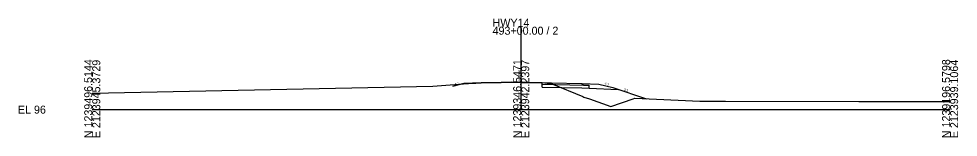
# Model space of a CAD drawing. Extents: x -26 to 303, y -10 to 11521.
# Drawn here: x -25.7 to 302.8, y 4490.3 to 4531.9 of the extents above; entities that cross this region are included whole.
import ezdxf

# ---------------------------------------------------------------- set-up
doc = ezdxf.new("R2010")
doc.units = 0
for name, color, linetype in [('XS_CELL', 7, 'Continuous'), ('XS_P_FINISHED_GRADE', 7, 'Continuous'), ('XS_P_SUBGRADE_GRANULAR', 7, 'Continuous'), ('XS_P_SUBGRADE_LEVELING', 7, 'Continuous'), ('XS_P_SUBGRADE_PAVEMENT', 7, 'Continuous'), ('XS_P_TX_FS_BS', 7, 'Continuous'), ('XS_X_GROUND', 7, 'Continuous'), ('XS_X_GROUND_TX', 7, 'Continuous')]:
    doc.layers.add(name, color=color, linetype=linetype)

msp = doc.modelspace()

# ---------------------------------------------------------------- linework, layer by layer
at = {"layer": 'XS_CELL'}
for p, q in [((150, 4500), (150, 4529.09)), ((0, 4500), (150, 4500)), ((150, 4500), (300, 4500))]:
    msp.add_line(p, q, dxfattribs=at)
at = {"layer": 'XS_P_FINISHED_GRADE'}
for p, q in [((130, 4509.12), (126, 4508.12)), ((136, 4509.36), (130, 4509.12)), ((150, 4509.64), (136, 4509.36)), ((150, 4509.64), (171.19, 4509.21)), ((171.19, 4509.21), (177.19, 4508.97)), ((177.19, 4508.97), (182, 4507.77)), ((177.19, 4508.97), (182, 4507.77)), ((182, 4507.77), (193.86, 4503.82)), ((182, 4507.77), (193.86, 4503.82))]:
    msp.add_line(p, q, dxfattribs=at)
at = {"layer": 'XS_P_SUBGRADE_GRANULAR'}
for p, q in [((136, 4509.23), (129.4, 4508.97)), ((157.3, 4508.91), (157.3, 4509.49)), ((157.3, 4508.91), (157.3, 4509.49)), ((157.3, 4507.91), (157.3, 4508.91)), ((157.3, 4507.91), (157.3, 4508.91)), ((157.3, 4507.91), (171.19, 4507.63)), ((157.3, 4507.91), (171.19, 4507.63)), ((171.19, 4507.63), (173.81, 4507.53)), ((171.19, 4507.63), (173.81, 4507.53)), ((171.81, 4508.62), (173.81, 4508.54)), ((171.81, 4508.62), (173.81, 4508.54)), ((173.81, 4507.53), (173.81, 4508.54)), ((173.81, 4507.53), (173.81, 4508.54)), ((173.81, 4507.53), (183.96, 4507.12)), ((173.81, 4507.53), (183.96, 4507.12))]:
    msp.add_line(p, q, dxfattribs=at)
at = {"layer": 'XS_P_SUBGRADE_LEVELING'}
for p, q in [((150, 4509.51), (136, 4509.23)), ((136, 4509.23), (136, 4509.36)), ((150, 4509.51), (157.3, 4509.37))]:
    msp.add_line(p, q, dxfattribs=at)
at = {"layer": 'XS_P_SUBGRADE_PAVEMENT'}
for p, q in [((157.3, 4508.91), (171.81, 4508.62)), ((157.3, 4508.91), (171.81, 4508.62)), ((171.19, 4509.21), (171.67, 4508.86)), ((171.19, 4509.21), (171.67, 4508.86)), ((171.67, 4508.86), (171.81, 4508.62)), ((171.67, 4508.86), (171.81, 4508.62))]:
    msp.add_line(p, q, dxfattribs=at)
at = {"layer": 'XS_X_GROUND'}
for p, q in [((0, 4505.74), (119.06, 4508.23)), ((119.06, 4508.23), (132.9, 4509.29)), ((132.9, 4509.29), (134.12, 4509.33)), ((134.12, 4509.33), (135.44, 4509.42)), ((135.44, 4509.42), (144.04, 4509.62)), ((144.04, 4509.62), (146.54, 4509.7)), ((146.54, 4509.7), (150, 4509.64)), ((150, 4509.64), (151.96, 4509.6)), ((151.96, 4509.6), (154.53, 4509.57)), ((154.53, 4509.57), (157.3, 4509.52)), ((157.3, 4509.52), (158.32, 4509.39)), ((157.3, 4509.52), (158.32, 4509.39)), ((158.32, 4509.39), (160.78, 4509.09)), ((158.32, 4509.39), (160.78, 4509.09)), ((160.78, 4509.09), (171.55, 4504.56)), ((160.78, 4509.09), (171.55, 4504.56)), ((171.55, 4504.56), (171.92, 4504.43)), ((171.55, 4504.56), (171.92, 4504.43)), ((171.92, 4504.43), (173.86, 4503.74)), ((171.92, 4504.43), (173.86, 4503.74)), ((173.86, 4503.74), (181.35, 4501.08)), ((173.86, 4503.74), (181.35, 4501.08)), ((181.35, 4501.08), (189.18, 4503.8)), ((181.35, 4501.08), (189.18, 4503.8)), ((189.18, 4503.8), (189.76, 4504)), ((189.18, 4503.8), (189.76, 4504)), ((189.76, 4504), (212.47, 4503.01)), ((212.47, 4503.01), (221.42, 4503)), ((221.42, 4503), (268.09, 4502.91)), ((268.09, 4502.91), (300, 4502.83))]:
    msp.add_line(p, q, dxfattribs=at)

# ---------------------------------------------------------------- texts
at = {"layer": 'XS_CELL'}
for s, p in [('HWY14', (140, 4529.09)), ('493+00.00 / 2', (140, 4526.29)), ('EL 96', (-26, 4498.6))]:
    msp.add_text(s, height=2.8, dxfattribs=at).set_placement(p)
for s, p in [('N 1239496.5144', (0, 4490)), ('N 1239346.5471', (150, 4490)), ('N 1239196.5798', (300, 4490)), ('E 2123939.1064', (302.8, 4490)), ('E 2123945.3729', (2.8, 4490)), ('E 2123942.2397', (152.8, 4490))]:
    msp.add_text(s, height=2.8, rotation=90, dxfattribs=at).set_placement(p)
at = {"layer": 'XS_P_TX_FS_BS'}
for s, rotation, p in [('4:1', 14.0362, (126.88, 4508.51)), ('4:1', 345.9638, (179.14, 4508.84)), ('4:1', 345.9638, (179.14, 4508.84)), ('3:1', 341.5651, (185.84, 4506.76)), ('3:1', 341.5651, (185.84, 4506.76))]:
    msp.add_text(s, height=0.8, rotation=rotation, dxfattribs=at).set_placement(p)
at = {"layer": 'XS_X_GROUND_TX'}
msp.add_text('105.64', height=1, rotation=90, dxfattribs=at).set_placement((150, 4509.74))

doc.saveas('drawing.dxf')
